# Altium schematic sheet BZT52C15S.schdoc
size 127 x 101 mm
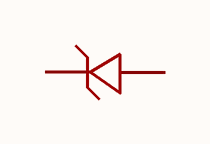
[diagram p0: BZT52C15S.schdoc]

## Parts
ZD?  bzt52c15s_c17283  [SOD-323_L1.8-W1.3-LS2.5-RD]  (value not drawn)

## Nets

Not connected (* = marked no-connect by the designer): ZD? 1(K) 2(A)

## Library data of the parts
ZD? = bzt52c15s_c17283: 二极管配置:1个独立式;稳压值(标称值):15V;稳压值(范围):13.8V~15.6V;耗散功率(Pd):200mW;; Manufacturer: CJ(江苏长电/长晶); AddInBom: yes; ModelId: db63db13d9e342eb939127d413d6200b; ModelTransform: 104.3305,51.181,0,0,0,0,0,-0.004,0; Diode Configuration: 1个独立式; Zener Voltage(Nom): 15V; Reverse Leakage Current (Ir): 100nA@1V; Pd - Power Dissipation: 200mW; Impedance(Zzt): 30Ω; Impedance(Zzk): 200Ω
